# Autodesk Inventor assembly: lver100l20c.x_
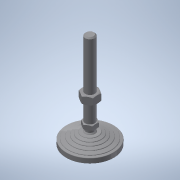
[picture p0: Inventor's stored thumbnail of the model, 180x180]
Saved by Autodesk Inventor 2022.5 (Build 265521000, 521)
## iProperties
Part Number: lver100l20c.x_
Material: 一般
Document SubType Name: Assembly
Designer: ImaoCorp
Sending System: SOLIDWORKS 2017-2017317
MC: AMD64
MC_MODEL: Intel64 Family 6 Model 60 Stepping 3, GenuineIntel
OS: Windows_NT
FRU: Parasolid Version 29.0, build 201,  4-17-2017
FORMAT: text
GUISE: transmit
KEY: lver100l20c
FILE: lver100l20c.x_t
DATE: Mon Jul 01 18:23:00 2019
Author: ImaoCorp
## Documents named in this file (3)
- X:\14_SW2022-Inv2022\00_全2023-1023新製品(TCC)まで\l\lver100l20c\LVER100L20C.iam
- X:\14_SW2022-Inv2022\00_全2023-1023新製品(TCC)まで\l\lver100l20c\lver100l20c_01.ipt
- X:\14_SW2022-Inv2022\00_全2023-1023新製品(TCC)まで\l\lver100l20c\lver100l20c_02.ipt
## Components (2 placed, 2 different names)
1. lver100l20c_01
2. lver100l20c_02
